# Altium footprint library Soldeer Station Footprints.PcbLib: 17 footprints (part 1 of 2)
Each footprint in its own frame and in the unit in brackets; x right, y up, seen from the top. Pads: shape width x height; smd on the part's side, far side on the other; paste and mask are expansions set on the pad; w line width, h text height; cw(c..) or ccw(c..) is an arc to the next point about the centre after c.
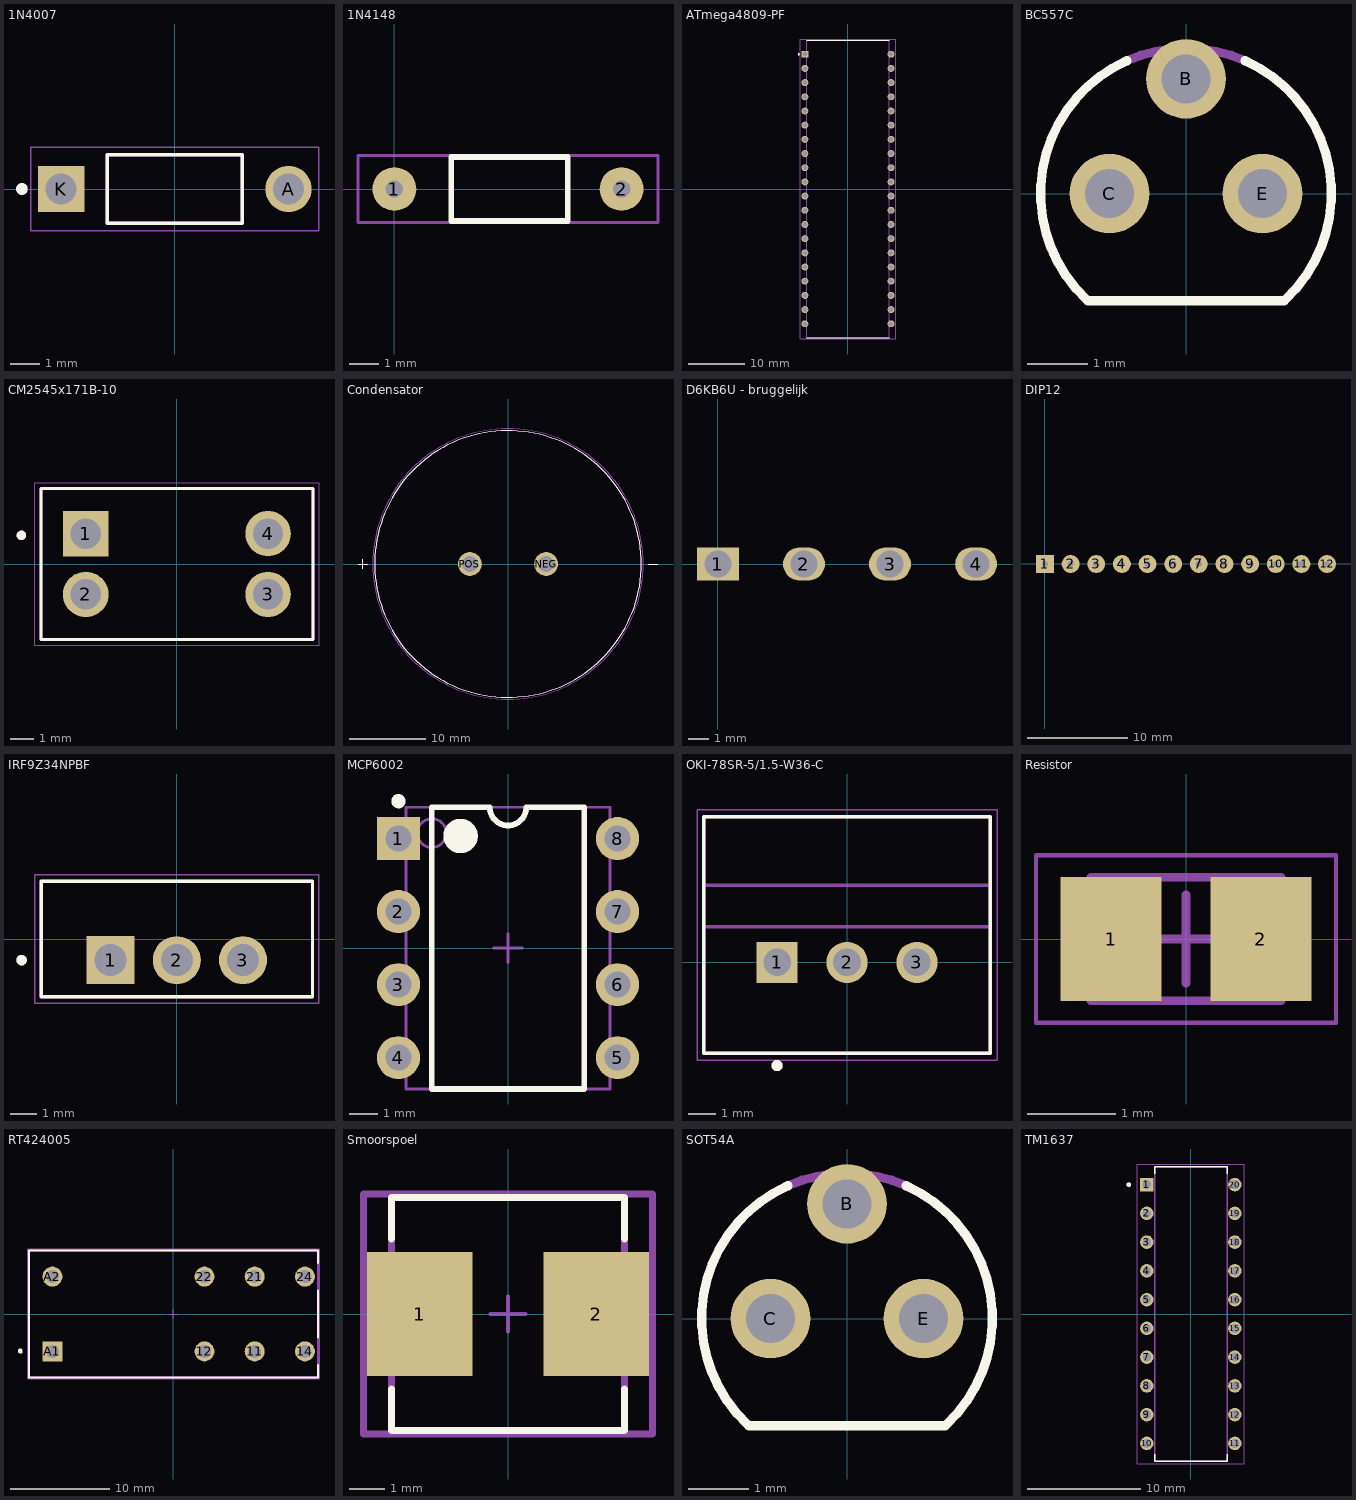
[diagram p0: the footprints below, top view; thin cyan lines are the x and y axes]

## 1N4007 [mm]
pads (2):
  round 1.59 hole 1.06: A(3.905,0)
  rect 1.59x1.59 / inner round 1.59 / far side rect 1.59x1.59 hole 1.06: K(-3.905,0)
Top Overlay:
  circle w0.2: c-5.25,0 r0.1
  lines w0.127: -2.318,-1.18 -2.318,1.18 2.318,1.18 2.318,-1.18 -2.318,-1.18
Mechanical 13:
  circle w0.2: c-5.25,0 r0.1
  lines w0.127: -2.318,-1.18 -2.318,1.18 2.318,1.18 2.318,-1.18 -2.318,-1.18
Mechanical 15:
  lines w0.05: -4.949,-1.43 4.949,-1.43 4.949,1.43 -4.949,1.43 -4.949,-1.43
3D body "step_temp.STEP": height 2.69, standoff -21.77, extent -5.474,-1.346 5.474,1.346

## 1N4148 [mm]
pads (2):
  round 1.5 hole 0.6: 1(0,0) 2(7.8,0)
Top Overlay:
  lines w0.2: 1.95,-1.1 1.95,1.1 5.95,1.1 5.95,-1.1 1.95,-1.1
Mechanical 15:
  lines w0.1: -1.25,-1.15 -1.25,1.15 9.05,1.15 9.05,-1.15 -1.25,-1.15
3D body "p0_DO-35.stp": height 1.95, standoff 0.05, extent -25.5,-0.95 33.4,0.95

## ATmega4809-PF [mm]
pads (40):
  rect 1.24x1.24 hole 0.89: 1(-7.715,24.13)
  round 1.24 hole 0.89: 2(-7.715,21.59) 3(-7.715,19.05) 4(-7.715,16.51) 5(-7.715,13.97) 6(-7.715,11.43) 7(-7.715,8.89) 8(-7.715,6.35) 9(-7.715,3.81) 10(-7.715,1.27) 11(-7.715,-1.27) 12(-7.715,-3.81) 13(-7.715,-6.35) 14(-7.715,-8.89) 15(-7.715,-11.43) 16(-7.715,-13.97) 17(-7.715,-16.51) 18(-7.715,-19.05) 19(-7.715,-21.59) 20(-7.715,-24.13) 21(7.715,-24.13) 22(7.715,-21.59) 23(7.715,-19.05) 24(7.715,-16.51) 25(7.715,-13.97) 26(7.715,-11.43) 27(7.715,-8.89) 28(7.715,-6.35) 29(7.715,-3.81) 30(7.715,-1.27) 31(7.715,1.27) 32(7.715,3.81) 33(7.715,6.35) 34(7.715,8.89) 35(7.715,11.43) 36(7.715,13.97) 37(7.715,16.51) 38(7.715,19.05) 39(7.715,21.59) 40(7.715,24.13)
Top Overlay:
  circle w0.2: c-8.835,24.13 r0.1
  lines w0.127: -7.366,-26.607 7.366,-26.607 ; -7.366,26.607 7.366,26.607
Mechanical 13:
  circle w0.2: c-8.835,24.13 r0.1
  lines w0.127: -7.366,-26.607 7.366,-26.607 7.366,26.607 -7.366,26.607 -7.366,-26.607
Mechanical 15:
  lines w0.05: -8.585,-26.856 8.585,-26.856 8.585,26.856 -8.585,26.856 -8.585,-26.856
3D body "step_temp.STEP": height 2.03, standoff -5.71, extent -8.255,-26.137 8.255,26.137

## BC557C [mil]
pads (3):
  round 52 hole 32: B(0,75) C(-50,0) E(50,0)
Top Overlay:
  lines w6: -64.78,-69.48 cw(c0.01,0) -38.63,86.79 ; -64.21,-70 64.21,-70 ; 38.63,86.79 cw(c-0.01,0) 64.78,-69.48
Mechanical 13:
  lines w6: -38.64,86.79 cw(c0,0) 38.64,86.79
3D body "step_temp.STEP": height 304.72, standoff -65.35, extent -94.45,-60.35 94.45,94.49

## CM2545x171B-10 [mil]
pads (4):
  rect 75x75 hole 50: 1(-150,50)
  round 75 hole 50: 2(-150,-50) 3(150,-50) 4(150,50)
Top Overlay:
  circle w7.87: c-255.91,47.24 r3.94
  lines w5: -224.02,-124.02 -224.02,124.02 224.02,124.02 224.02,-124.02 -224.02,-124.02
Mechanical 13:
  circle w7.87: c-255.91,47.24 r3.94
  lines w5: -224.02,-124.02 -224.02,124.02 224.02,124.02 224.02,-124.02 -224.02,-124.02
Mechanical 15:
  lines w1.97: -233.86,-133.86 233.86,-133.86 233.86,133.86 -233.86,133.86 -233.86,-133.86
3D body "step_temp.STEP": height 374.02, standoff -144.88, extent -224.02,-124.02 224.02,124.02

## Condensator [mm]
pads (2):
  round 3.116 hole 2.1: NEG(5,0) POS(-5,0)
Top Overlay:
  circle w0.127: c0,0 r17.5
  lines w0.127: -19.685,0 -18.415,0 ; -19.05,-0.635 -19.05,0.635 ; 18.415,0 19.685,0
Mechanical 13:
  circle w0.127: c0,0 r17.5
  lines w0.127: -19.685,0 -18.415,0 ; -19.05,-0.635 -19.05,0.635 ; 18.415,0 19.685,0
Mechanical 15:
  circle w0.05: c0,0 r17.75

## D6KB6U - bruggelijk [mm]
pads (4):
  rect 2x1.6 hole 1.3: 1(0,0)
  oval 2x1.6 hole 1.3: 2(4.11,0) 3(8.22,0) 4(12.33,0)

## DIP12 [mil]
pads (12):
  rect 70x70 hole 25: 1(0,0)
  round 70 hole 25: 2(100,0) 3(200,0) 4(300,0) 5(400,0) 6(500,0) 7(600,0) 8(700,0) 9(800,0) 10(900,0) 11(1000,0) 12(1100,0)

## IRF9Z34NPBF [mm]
pads (3):
  rect 1.845x1.845 / inner round 1.845 / far side rect 1.845x1.845 hole 1.23: 1(-2.54,-0.81)
  round 1.845 hole 1.23: 2(0,-0.81) 3(2.54,-0.81)
Top Overlay:
  circle w0.2: c-5.957,-0.81 r0.1
  lines w0.127: -5.208,-2.222 5.208,-2.222 5.208,2.222 -5.208,2.222 -5.208,-2.222
Mechanical 13:
  circle w0.2: c-5.957,-0.81 r0.1
  lines w0.127: -5.208,-2.222 5.208,-2.222 5.208,2.222 -5.208,2.222 -5.208,-2.222
Mechanical 15:
  lines w0.05: -5.457,-2.472 -5.457,2.472 5.457,2.472 5.457,-2.472 -5.457,-2.472

## MCP6002 [mm]
height 5.34
pads (8):
  rect 1.5x1.5 hole 0.9: 1(-3.81,3.81)
  round 1.5 hole 0.9: 2(-3.81,1.27) 3(-3.81,-1.27) 4(-3.81,-3.81) 5(3.81,-3.81) 6(3.81,-1.27) 7(3.81,1.27) 8(3.81,3.81)
Top Overlay:
  circle w0.6: c-1.65,3.9 r0.3
  circle w0.25: c-3.81,5.11 r0.125
  lines w0.2: -2.65,-4.9 2.65,-4.9 2.65,4.9 0.635,4.9 cw(c0,4.9) -0.635,4.9 -2.65,4.9 -2.65,-4.9
Mechanical 13:
  circle w0.1: c-2.65,4 r0.5
  lines w0.1: -3.55,-4.9 3.55,-4.9 3.55,4.9 -3.55,4.9 -3.55,-4.9
Mechanical 15:
  lines w0.1: -0.5,0 0.5,0 ; 0,-0.5 0,0.5
3D body: height 4.32, standoff 0, extent -3.55,-4.9 3.55,4.9

## OKI-78SR-5/1.5-W36-C [mm]
pads (3):
  rect 1.5x1.5 hole 1: 1(-2.54,0)
  round 1.5 hole 1: 2(0,0) 3(2.54,0)
Top Overlay:
  circle w0.2: c-2.54,-3.75 r0.1
  lines w0.127: -5.2,-3.3 -5.2,5.3 5.2,5.3 5.2,-3.3 -5.2,-3.3
Mechanical 13:
  circle w0.2: c-2.54,-3.75 r0.1
  lines w0.127: -5.2,1.3 5.2,1.3 ; -5.2,1.3 -5.2,2.8 ; -5.2,1.3 -5.2,-3.3 5.2,-3.3 5.2,1.3 ; -5.2,2.8 5.2,2.8 ; -5.2,2.8 -5.2,5.3 5.2,5.3 5.2,2.8 ; 5.2,1.3 5.2,2.8
Mechanical 15:
  lines w0.05: -5.45,-3.55 -5.45,5.55 5.45,5.55 5.45,-3.55 -5.45,-3.55

## Resistor [mm] "Chip Resistor, 2-Leads, Body 2,00x1,25mm, IPC Medium Density"
height 0.6
pads (2):
  rect 1.15x1.4 smd: 1(-0.85,0) 2(0.85,0)
Mechanical 13:
  lines w0.1: -1.075,-0.7 -1.075,0.7 1.075,0.7 1.075,-0.7 -1.075,-0.7
Mechanical 15:
  lines w0.05: -1.7,-0.95 -1.7,0.95 1.7,0.95 1.7,-0.95 -1.7,-0.95
  lines w0.1: -0.5,0 0.5,0 ; 0,-0.5 0,0.5
3D body: height 0.6, standoff 0, extent -0.525,-0.7 0.525,0.7
3D body: height 0.6, standoff 0, extent -1.075,-0.7 -0.525,0.7
3D body: height 0.6, standoff 0, extent 0.525,-0.7 1.075,0.7

## RT424005 [mm]
pads (8):
  round 2 hole 1.3 paste-2539.97 mask+0: 11(8.15,-3.75) 12(3.11,-3.75) 14(13.19,-3.75) 21(8.15,3.75) 22(3.11,3.75) 24(13.19,3.75) A2(-12.15,3.75)
  rect 2x2 hole 1.3 paste-2539.97 mask+0: A1(-12.15,-3.75)
Top Overlay:
  circle w0.25: c-15.375,-3.725 r0.125
  lines w0.2: 14.5,-5.125 14.5,-6.35 -14.5,-6.35 -14.5,6.35 14.5,6.35 14.5,5.125 ; 14.5,-2.375 14.5,2.375
Top 3D Body:
  lines w0.2: -14.5,-6.35 -14.5,6.35 14.5,6.35 14.5,-6.35 -14.5,-6.35
Top Courtyard:
  lines w0.2: -14.6,-6.45 -14.6,6.45 14.6,6.45 14.6,-6.45 -14.6,-6.45
Top Assembly:
  lines w0.2: -14.6,-6.45 -14.6,6.45 14.6,6.45 14.6,-6.45 -14.6,-6.45
  text ".Designator" at 0,0.188 h1
Top Component Center:
  lines w0.1: -0.5,0 0.5,0 ; 0,-0.5 0,0.5
3D body "Relay_TE_Connectivity_RT424005_eec.STEP": height 0.25, standoff 0, extent -14.6,-6.45 14.6,6.45

## Smoorspoel [mm]
pads (2):
  rect 3x3.5 smd paste+0 mask+0: 1(-2.5,0) 2(2.5,0)
Top Overlay:
  lines w0.2: -3.3,-2.125 -3.3,-3.3 3.3,-3.3 3.3,-2.125 ; -3.3,2.125 -3.3,3.3 3.3,3.3 3.3,2.125
Top 3D Body:
  lines w0.2: -3.3,-3.3 -3.3,3.3 3.3,3.3 3.3,-3.3 -3.3,-3.3
Top Courtyard:
  lines w0.2: -4.1,-3.4 -4.1,3.4 4.1,3.4 4.1,-3.4 -4.1,-3.4
Top Assembly:
  lines w0.2: -4.1,-3.4 -4.1,3.4 4.1,3.4 4.1,-3.4 -4.1,-3.4
  text ".Designator" at 0,0.188 h1
Top Component Center:
  lines w0.1: -0.5,0 0.5,0 ; 0,-0.5 0,0.5
3D body "Ind_Murata_LQH66SN100M03L_eec.STEP": height 0.25, standoff 0, extent -4.1,-3.4 4.1,3.4

## SOT54A [mil]
pads (3):
  round 52 hole 32: B(0,75) C(-50,0) E(50,0)
Top Overlay:
  lines w6: -64.78,-69.48 cw(c0.01,0) -38.63,86.79 ; -64.21,-70 64.21,-70 ; 38.63,86.79 cw(c-0.01,0) 64.78,-69.48
Mechanical 13:
  lines w6: -38.64,86.79 cw(c0,0) 38.64,86.79
3D body "step_temp.STEP": height 304.72, standoff -65.35, extent -94.45,-60.35 94.45,94.49

## TM1637 [mm]
pads (20):
  rect 1.19x1.19 hole 0.79: 1(-3.89,11.43)
  round 1.19 hole 0.79: 2(-3.89,8.89) 3(-3.89,6.35) 4(-3.89,3.81) 5(-3.89,1.27) 6(-3.89,-1.27) 7(-3.89,-3.81) 8(-3.89,-6.35) 9(-3.89,-8.89) 10(-3.89,-11.43) 11(3.89,-11.43) 12(3.89,-8.89) 13(3.89,-6.35) 14(3.89,-3.81) 15(3.89,-1.27) 16(3.89,1.27) 17(3.89,3.81) 18(3.89,6.35) 19(3.89,8.89) 20(3.89,11.43)
Top Overlay:
  circle w0.2: c-5.485,11.43 r0.1
  lines w0.127: -3.2,-12.375 -3.2,-13 3.2,-13 3.2,-12.375 ; -3.2,12.375 -3.2,13 3.2,13 3.2,12.375
Mechanical 13:
  circle w0.2: c-5.485,11.43 r0.1
  lines w0.127: -3.2,-13 3.2,-13 3.2,13 -3.2,13 -3.2,-13
Mechanical 15:
  lines w0.05: -4.735,-13.25 -4.735,13.25 4.735,13.25 4.735,-13.25 -4.735,-13.25
3D body "step_temp.STEP": height 4.31, standoff -3.6, extent -4.03,-13 4.03,13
